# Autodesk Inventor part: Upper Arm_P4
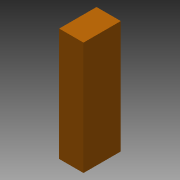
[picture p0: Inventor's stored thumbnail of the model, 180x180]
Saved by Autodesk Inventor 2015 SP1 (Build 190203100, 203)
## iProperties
Created: 2008-11
Part Number: Upper Arm_P4
Document SubType Name: Modeling
Designer: dwoollam
Density: 7.85 g/cm^3
Material: Steel
Appearance: Orange
Mass: 153585 g
Surface Area: 5217 cm^2
Volume: 19565 cm^3
Dwg_Category: Clearance_Mewp
INSTALLATION: False
CIVIL_WORK: False
EARTHING: False
MOUNTING: False
Author: dwoollam
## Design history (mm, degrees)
sketch "Sketch1"
  geometry: L1 (-70, 107.5)-(70, 107.5); L2 (70, 107.5)-(70, -107.5); L3 (70, -107.5)-(-70, -107.5); L4 (-70, -107.5)-(-70, 107.5); 3 further points
  constraints: 8 end point, 2 midpoint, 2 parallel, 1 horizontal, 1 horizontal alignment, 1 perpendicular, 1 vertical alignment
  dimensions: "d0" = 140 distance of L1.start L1.end; "d1" = 215 distance of L3.end L1.start
extrude "End Stop 2" new body sketch "Sketch1" stored distance "d2" = 650; taper "d3" = 0 deg
body "Solid1"
